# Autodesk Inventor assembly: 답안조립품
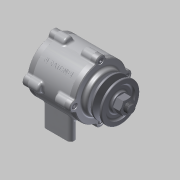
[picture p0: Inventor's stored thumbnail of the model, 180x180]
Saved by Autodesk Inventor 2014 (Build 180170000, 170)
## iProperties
Created: 2015-03
Part Number: 답안조립품
Document SubType Name: Assembly
Designer: MYHOME
Author: MYHOME
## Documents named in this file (11)
- C:\Documents and Settings\MYHOME\바탕 화면\450306V1022\답안조립품.iam
- C:\Documents and Settings\MYHOME\바탕 화면\450306V1022\본체.ipt
- C:\Documents and Settings\MYHOME\바탕 화면\450306V1022\커버.ipt
- C:\Documents and Settings\MYHOME\바탕 화면\450306V1022\M 4 x 12.ipt
- C:\Documents and Settings\MYHOME\바탕 화면\450306V1022\오일실.ipt
- C:\Documents and Settings\MYHOME\바탕 화면\450306V1022\커버2.ipt
- C:\Documents and Settings\MYHOME\바탕 화면\450306V1022\축.ipt
- C:\Documents and Settings\MYHOME\바탕 화면\450306V1022\키(4 x 4 x 12).ipt
- C:\Documents and Settings\MYHOME\바탕 화면\450306V1022\베어링 6204.ipt
- C:\Documents and Settings\MYHOME\바탕 화면\450306V1022\V벨트풀리.ipt
- C:\Documents and Settings\MYHOME\바탕 화면\450306V1022\너트 M12x1.25.ipt
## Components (14 placed, 6 different names)
1. KS B 2804 D D - 20 32 8:1
2. KS B 1311 (I) 4 x 4 x 12:1
3. KS B 2023 6204 - 20 x 47 x 14:1 — 각도:2
4. KS B 2023 6204 - 20 x 47 x 14:2 — 각도:1
5. 그루브 풀리1:1
6. KS B 1012 클래스 1 일반 - 미터 M12x1.25:1 — 각도:3
7. KS B 1003 - 미터 M 4 x 12:1
8. KS B 1003 - 미터 M 4 x 12:2
9. KS B 1003 - 미터 M 4 x 12:3
10. KS B 1003 - 미터 M 4 x 12:4
11. KS B 1003 - 미터 M 4 x 12:5
12. KS B 1003 - 미터 M 4 x 12:6
13. KS B 1003 - 미터 M 4 x 12:7
14. KS B 1003 - 미터 M 4 x 12:8
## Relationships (3: Angle 3)
- 각도:1 [Angle]: KS B 2023 6204 - 20 x 47 x 14:2
- 각도:2 [Angle]: KS B 2023 6204 - 20 x 47 x 14:1
- 각도:3 [Angle]: KS B 1012 클래스 1 일반 - 미터 M12x1.25:1
